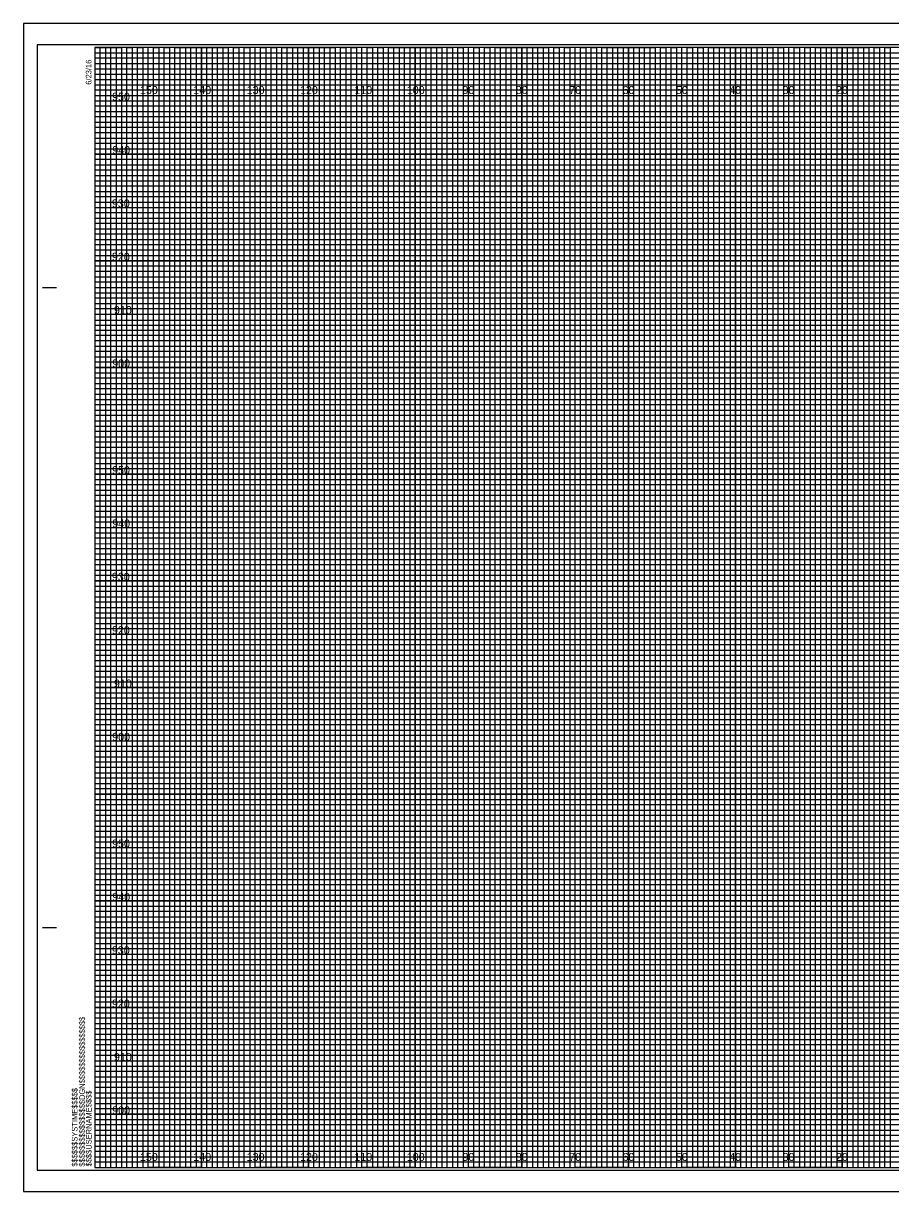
# Model space of a CAD drawing. Extents: x -13 to 323, y -4 to 3074.
# Drawn here: x -13.4 to 149.1, y 1975.5 to 2194.5 of the extents above; entities that cross this region are included whole.
import ezdxf

# ---------------------------------------------------------------- set-up
doc = ezdxf.new("R2010")
doc.units = 0
for name, color, linetype in [('Prop XS Elevation Labels', 7, 'Continuous'), ('Prop XS Offset Labels', 7, 'Continuous'), ('Sheet Cross Section CELL', 7, 'Continuous'), ('Sheet Cross Section Grid Major CELL', 7, 'Continuous'), ('Sheet Cross Section Grid Middle CELL', 7, 'Continuous'), ('Sheet Cross Section Grid Minor 1 CELL', 7, 'Continuous'), ('Sheet Cross Section Grid Minor 2 CELL', 7, 'Continuous'), ('Sheet Cutting Line CELL', 7, 'Continuous'), ('Sheet DOT Grid CELL', 7, 'Continuous'), ('Sheet Plot Border Inside CELL', 7, 'Continuous'), ('Sheet Plot Border Outside CELL', 7, 'Continuous')]:
    doc.layers.add(name, color=color, linetype=linetype)

msp = doc.modelspace()

# ---------------------------------------------------------------- linework, layer by layer
at = {"layer": 'Sheet Cross Section CELL'}
for p, q in [((-9.8, 2145), (-7.3, 2145)), ((-9.7, 2145), (-7.2, 2145)), ((-9.8, 2025), (-7.3, 2025)), ((-9.7, 2025), (-7.2, 2025)), ((0, 1980), (0, 1980)), ((0, 1980), (0, 1980)), ((0, 1980), (0, 1980)), ((0, 1980), (0, 1980)), ((0, 1980), (0, 1980)), ((0, 1980), (0, 1980)), ((0, 1980), (0, 1980))]:
    msp.add_line(p, q, dxfattribs=at)
msp.add_lwpolyline([(320, 2190), (0, 2190), (0, 1980), (320, 1980)], close=True, dxfattribs=at)
at = {"layer": 'Sheet Cross Section Grid Major CELL'}
for p, q in [((10, 2190), (0, 2190)), ((10, 1980), (10, 2190)), ((30, 2190), (20, 2190)), ((20, 2190), (20, 1980)), ((30, 1980), (30, 2190)), ((50, 2190), (40, 2190)), ((40, 2190), (40, 1980)), ((50, 1980), (50, 2190)), ((70, 2190), (60, 2190)), ((60, 2190), (60, 1980)), ((70, 1980), (70, 2190)), ((90, 2190), (80, 2190)), ((80, 2190), (80, 1980)), ((90, 1980), (90, 2190)), ((110, 2190), (100, 2190)), ((100, 2190), (100, 1980)), ((110, 1980), (110, 2190)), ((130, 2190), (120, 2190)), ((120, 2190), (120, 1980)), ((130, 1980), (130, 2190)), ((150, 2190), (140, 2190)), ((140, 2190), (140, 1980)), ((20, 1980), (10, 1980)), ((40, 1980), (30, 1980)), ((60, 1980), (50, 1980)), ((80, 1980), (70, 1980)), ((100, 1980), (90, 1980)), ((120, 1980), (110, 1980)), ((140, 1980), (130, 1980))]:
    msp.add_line(p, q, dxfattribs=at)
for points in [[(0, 2180), (320, 2180), (320, 2170), (0, 2170)], [(0, 2160), (320, 2160), (320, 2150), (0, 2150)], [(0, 2140), (320, 2140), (320, 2130), (0, 2130)], [(0, 2120), (320, 2120), (320, 2110), (0, 2110)], [(0, 2100), (320, 2100), (320, 2090), (0, 2090)], [(0, 2080), (320, 2080), (320, 2070), (0, 2070)], [(0, 2060), (320, 2060), (320, 2050), (0, 2050)], [(0, 2040), (320, 2040), (320, 2030), (0, 2030)], [(0, 2020), (320, 2020), (320, 2010), (0, 2010)], [(0, 2000), (320, 2000), (320, 1990), (0, 1990)]]:
    msp.add_lwpolyline(points, dxfattribs=at)
at = {"layer": 'Sheet Cross Section Grid Middle CELL'}
for points in [[(0, 2190), (5, 2190), (5, 1980), (15, 1980), (15, 2190), (25, 2190), (25, 1980), (35, 1980), (35, 2190), (45, 2190), (45, 1980), (55, 1980), (55, 2190), (65, 2190), (65, 1980), (75, 1980), (75, 2190), (85, 2190), (85, 1980), (95, 1980), (95, 2190), (105, 2190), (105, 1980), (115, 1980), (115, 2190), (125, 2190), (125, 1980), (135, 1980), (135, 2190), (145, 2190), (145, 1980), (155, 1980)], [(0, 2185), (275, 2185)], [(0, 2165), (320, 2165), (320, 2175), (0, 2175)], [(0, 2145), (320, 2145), (320, 2155), (0, 2155)], [(0, 2125), (320, 2125), (320, 2135), (0, 2135)], [(0, 2105), (320, 2105), (320, 2115), (0, 2115)], [(0, 2085), (320, 2085), (320, 2095), (0, 2095)], [(0, 2065), (320, 2065), (320, 2075), (0, 2075)], [(0, 2045), (320, 2045), (320, 2055), (0, 2055)], [(0, 2025), (320, 2025), (320, 2035), (0, 2035)], [(0, 2005), (320, 2005), (320, 2015), (0, 2015)], [(0, 1985), (320, 1985), (320, 1995), (0, 1995)]]:
    msp.add_lwpolyline(points, dxfattribs=at)
at = {"layer": 'Sheet Cross Section Grid Minor 1 CELL'}
for p, q in [((0, 2189), (260, 2189)), ((260, 2187.98), (0, 2187.98)), ((0, 2187.98), (0, 2187)), ((0, 2187), (260, 2187)), ((260, 2185.89), (0, 2185.89)), ((0, 2185.89), (0, 2184)), ((0, 2184), (320, 2184))]:
    msp.add_line(p, q, dxfattribs=at)
for points in [[(0, 2183), (270, 2183), (320, 2183), (320, 2182), (0, 2182)], [(0, 2181), (320, 2181), (320, 2179), (0, 2179)], [(0, 2178), (320, 2178), (320, 2177), (0, 2176.98)], [(0, 2176), (320, 2176), (320, 2174), (0, 2174)], [(0, 2173), (320, 2173), (320, 2172), (0, 2172)], [(0, 2171), (320, 2171), (320, 2169), (0, 2169)], [(0, 2168), (320, 2168), (320, 2167), (0, 2167)], [(0, 2166), (320, 2166), (320, 2164), (0, 2164)], [(0, 2163), (320, 2163), (320, 2162), (0, 2162)], [(0, 2161), (320, 2161), (320, 2159), (0, 2159)], [(0, 2158), (320, 2158), (320, 2157), (0, 2157)], [(0, 2156), (320, 2156), (320, 2153.95), (320, 2153), (320, 2152), (0, 2152)], [(0, 2154), (320, 2154), (320, 2153), (0, 2153)], [(0, 2151), (320, 2151), (320, 2149), (0, 2149.03)], [(0, 2149.03), (320, 2149), (320, 2148), (0, 2148)], [(0, 2147), (320, 2147), (320, 2146), (0, 2146)], [(0, 2144), (320, 2144), (320, 2143), (0, 2143)], [(0, 2142), (320, 2142), (320, 2141), (0, 2141)], [(-0.07, 2138.89), (320, 2138.89), (320, 2137.88), (-0.07, 2137.88)], [(0, 2137), (320, 2137), (320, 2136), (0, 2136)], [(0, 2134), (320, 2134), (320, 2133), (0, 2133)], [(0, 2132), (320, 2132), (320, 2131), (0, 2131)], [(0, 2129), (320, 2129), (320, 2128), (0, 2128)], [(0, 2127), (320, 2127), (320, 2126), (0, 2126)], [(0, 2124), (320, 2124), (320, 2123), (0, 2123)], [(0, 2122), (320, 2122), (320, 2121), (0, 2121)], [(0, 2119), (320, 2119), (319.99, 2117.98), (0, 2118)], [(0, 2117), (320, 2117), (320, 2116), (0, 2116)], [(0, 2114), (320, 2114), (320, 2113), (0, 2113)], [(0, 2112), (320, 2112), (320, 2111), (0, 2111)], [(0, 2109), (320, 2109), (320, 2108), (0, 2108)], [(0, 2107), (320, 2107), (320, 2106), (0, 2106)], [(0, 2104), (320, 2104), (320, 2103), (0, 2103)], [(0, 2102), (320, 2102), (320, 2101), (0, 2101)], [(0, 2099), (320, 2099), (320, 2098), (0, 2098)], [(0, 2096.99), (320.07, 2096.91), (320, 2096), (0, 2096)], [(0, 2094), (320, 2094), (320, 2093), (0, 2093)], [(0, 2092), (320, 2092), (320, 2091), (0, 2091)], [(0, 2089), (320, 2089), (320, 2088), (0, 2088)], [(0, 2087), (320, 2087), (320, 2086), (0, 2086)], [(0, 2084), (320, 2084), (320, 2083), (0, 2083)], [(0, 2082), (320, 2082), (320, 2081), (0, 2081)], [(0, 2079), (320, 2079), (320, 2078), (0, 2078)], [(0, 2077), (320, 2077), (320, 2076), (0, 2076)], [(0, 2074), (320, 2074), (320, 2073), (0, 2073)], [(0, 2072), (320, 2072), (320, 2071), (0, 2071)], [(0, 2069), (320, 2069), (320, 2068), (0, 2068)], [(0, 2067), (320, 2067), (320, 2066), (0, 2066)], [(0, 2064), (320, 2064), (320, 2063), (0, 2063)], [(0, 2062), (320, 2062), (320, 2061), (0, 2061)], [(0, 2059), (320, 2059), (319.99, 2057.98), (0, 2058)], [(0, 2057), (320, 2057), (320, 2056), (0, 2056)], [(0, 2054), (320, 2054), (320, 2053), (0, 2053)], [(0, 2052), (320, 2052), (320, 2051), (0, 2051)], [(0, 2049), (320, 2049), (320, 2048), (0, 2048)], [(0, 2047), (320, 2047), (320, 2046), (0, 2046)], [(0, 2044), (320, 2044), (320, 2043), (0, 2043)], [(0, 2042), (320, 2042), (320, 2041), (0, 2041)], [(0, 2039), (320, 2039), (320, 2038), (0, 2038)], [(0, 2036.99), (320.07, 2036.91), (320, 2036), (0, 2036)], [(0, 2034), (320, 2034), (320, 2033), (0, 2033)], [(0, 2032), (320, 2032), (320, 2031), (0, 2031)], [(0, 2029), (320, 2029), (320, 2028), (0, 2028)], [(0, 2027), (320, 2027), (320, 2026), (0, 2026)], [(0, 2024), (320, 2024), (320, 2023), (0, 2023)], [(0, 2022), (320, 2022), (320, 2021), (0, 2021)], [(0, 2019), (320, 2019), (320, 2018), (0, 2018)], [(0, 2017), (320, 2017), (320, 2016), (0, 2016)], [(0, 2014), (320, 2014), (320, 2013), (0, 2013)], [(0, 2012), (320, 2012), (320, 2011), (0, 2011)], [(0, 2009), (320, 2009), (320, 2008), (0, 2008)], [(0, 2007), (320, 2007), (320, 2006), (0, 2006)], [(0, 2004), (320, 2004), (320, 2003), (0, 2003)], [(0, 2002), (320, 2002), (320, 2001), (0, 2001)], [(0, 1999), (320, 1999), (320, 1998), (0, 1998)], [(0, 1997), (320, 1997), (320, 1996), (0, 1996)], [(0, 1994), (320, 1994), (320, 1993), (0, 1993)], [(0, 1992), (320, 1992), (320, 1991), (0, 1991)], [(0, 1989), (320, 1989), (320, 1988), (0, 1988)], [(0, 1987), (320, 1987), (320, 1986), (0, 1986)], [(0, 1984), (320, 1984), (320, 1983), (0, 1983)], [(0, 1982), (320, 1982), (320, 1981), (0, 1981)]]:
    msp.add_lwpolyline(points, dxfattribs=at)
at = {"layer": 'Sheet Cross Section Grid Minor 2 CELL'}
for points in [[(0, 1980), (1, 1980), (1, 2190), (2, 2190), (2, 1980)], [(2, 1980), (3, 1980), (3, 2190), (4, 2190), (4, 1980)], [(5, 1980), (6, 1980), (6, 2190), (7, 2190), (7, 1980)], [(7, 1980), (8, 1980), (8, 2190), (9, 2190), (9, 1980)], [(10, 1980), (11, 1980), (11, 2190), (12, 2190), (12, 1980)], [(12, 1980), (13, 1980), (13, 2190), (14, 2190), (14, 1980)], [(15, 1980), (16, 1980), (16, 2190), (17, 2190), (17, 1980)], [(17, 1980), (18, 1980), (18, 2190), (19, 2190), (19, 1980)], [(20, 1980), (21, 1980), (21, 2190), (22, 2190), (22, 1980)], [(22, 1980), (23, 1980), (23, 2190), (24, 2190), (24, 1980)], [(25, 1980), (26, 1980), (26, 2190), (27, 2190), (27, 1980)], [(27, 1980), (28, 1980), (28, 2190), (29, 2190), (29, 1980)], [(30, 1980), (31, 1980), (31, 2190), (32, 2190), (32, 1980)], [(32, 1980), (33, 1980), (33, 2190), (34, 2190), (34, 1980)], [(35, 1980), (36, 1980), (36, 2190), (37, 2190), (37, 1980)], [(37, 1980), (38, 1980), (38, 2190), (39, 2190), (39, 1980)], [(40, 1980), (41, 1980), (41, 2190), (42, 2190), (42, 1980)], [(42, 1980), (43, 1980), (43, 2190), (44, 2190), (44, 1980)], [(45, 1980), (46, 1980), (46, 2190), (47, 2190), (47, 1980)], [(47, 1980), (48, 1980), (48, 2190), (49, 2190), (49, 1980)], [(50, 1980), (51, 1980), (51, 2190), (52, 2190), (52, 1980)], [(52, 1980), (53, 1980), (53, 2190), (54, 2190), (54, 1980)], [(55, 1980), (56, 1980), (56, 2190), (57, 2190), (57, 1980)], [(57, 1980), (58, 1980), (58, 2190), (59, 2190), (59, 1980)], [(60, 1980), (61, 1980), (61, 2190), (62, 2190), (62, 1980)], [(62, 1980), (63, 1980), (63, 2190), (64, 2190), (64, 1980)], [(65, 1980), (66, 1980), (66, 2190), (67, 2190), (67, 1980)], [(67, 1980), (68, 1980), (68, 2190), (69, 2190), (69, 1980)], [(70, 1980), (71, 1980), (71, 2190), (72, 2190), (72, 1980)], [(72, 1980), (73, 1980), (73, 2190), (74, 2190), (74, 1980)], [(75, 1980), (76, 1980), (76, 2190), (77, 2190), (77, 1980)], [(77, 1980), (78, 1980), (78, 2190), (79, 2190), (79, 1980)], [(80, 1980), (81, 1980), (81, 2190), (82, 2190), (82, 1980)], [(82, 1980), (83, 1980), (83, 2190), (84, 2190), (84, 1980)], [(85, 1980), (86, 1980), (86, 2190), (87, 2190), (87, 1980)], [(87, 1980), (88, 1980), (88, 2190), (89, 2190), (89, 1980)], [(90, 1980), (91, 1980), (91, 2190), (92, 2190), (92, 1980)], [(92, 1980), (93, 1980), (93, 2190), (94, 2190), (94, 1980)], [(95, 1980), (96, 1980), (96, 2190), (97, 2190), (97, 1980)], [(97, 1980), (98, 1980), (98, 2190), (99, 2190), (99, 1980)], [(100, 1980), (101, 1980), (101, 2190), (102, 2190), (102, 1980)], [(102, 1980), (103, 1980), (103, 2190), (104, 2190), (104, 1980)], [(105, 1980), (106, 1980), (106, 2190), (107, 2190), (107, 1980)], [(107, 1980), (108, 1980), (108, 2190), (109, 2190), (109, 1980)], [(110, 1980), (111, 1980), (111, 2190), (112, 2190), (112, 1980)], [(112, 1980), (113, 1980), (113, 2190), (114, 2190), (114, 1980)], [(115, 1980), (116, 1980), (116, 2190), (117, 2190), (117, 1980)], [(117, 1980), (118, 1980), (118, 2190), (119, 2190), (119, 1980)], [(120, 1980), (121, 1980), (121, 2190), (122, 2190), (122, 1980)], [(122, 1980), (123, 1980), (123, 2190), (124, 2190), (124, 1980)], [(125, 1980), (126, 1980), (126, 2190), (127, 2190), (127, 1980)], [(127, 1980), (128, 1980), (128, 2190), (129, 2190), (129, 1980)], [(130, 1980), (131, 1980), (131, 2190), (132, 2190), (132, 1980)], [(132, 1980), (133, 1980), (133, 2190), (134, 2190), (134, 1980)], [(135, 1980), (136, 1980), (136, 2190), (137, 2190), (137, 1980)], [(137, 1980), (138, 1980), (138, 2190), (139, 2190), (139, 1980)], [(140, 1980), (141, 1980), (141, 2190), (142, 2190), (142, 1980)], [(142, 1980), (143, 1980), (143, 2190), (144, 2190), (144, 1980)], [(145, 1980), (146, 1980), (146, 2190), (147, 2190), (147, 1980)], [(147, 1980), (148, 1980), (148, 2190), (149, 2190), (149, 1980)]]:
    msp.add_lwpolyline(points, dxfattribs=at)
at = {"layer": 'Sheet Cutting Line CELL'}
for p, q in [((323.3, 2194.5), (-13.4, 2194.5)), ((-13.4, 2194.5), (-13.4, 1975.5)), ((-13.4, 1975.5), (323.3, 1975.5))]:
    msp.add_line(p, q, dxfattribs=at)
at = {"layer": 'Sheet DOT Grid CELL'}
for p, q in [((10, 1980), (10, 2190)), ((20, 1980), (20, 2190)), ((30, 1980), (30, 2190)), ((40, 1980), (40, 2190)), ((50, 1980), (50, 2190)), ((60, 1980), (60, 2190)), ((70, 1980), (70, 2190)), ((80, 1980), (80, 2190)), ((90, 1980), (90, 2190)), ((100, 1980), (100, 2190)), ((110, 1980), (110, 2190)), ((120, 1980), (120, 2190)), ((130, 1980), (130, 2190)), ((140, 1980), (140, 2190)), ((0, 2180), (320, 2180)), ((0, 2170), (320, 2170)), ((0, 2160), (320, 2160)), ((0, 2150), (320, 2150)), ((0, 2140), (320, 2140)), ((0, 2130), (320, 2130)), ((0, 2120), (320, 2120)), ((0, 2110), (320, 2110)), ((0, 2100), (320, 2100)), ((0, 2090), (320, 2090)), ((0, 2080), (320, 2080)), ((0, 2070), (320, 2070)), ((0, 2060), (320, 2060)), ((0, 2050), (320, 2050)), ((0, 2040), (320, 2040)), ((0, 2030), (320, 2030)), ((0, 2020), (320, 2020)), ((0, 2010), (320, 2010)), ((0, 2000), (320, 2000)), ((0, 1990), (320, 1990))]:
    msp.add_line(p, q, dxfattribs=at)
at = {"layer": 'Sheet Plot Border Inside CELL'}
msp.add_lwpolyline([(-10.8, 1979.5), (322.4, 1979.5), (322.4, 2190.5), (-10.8, 2190.5)], close=True, dxfattribs=at)
at = {"layer": 'Sheet Plot Border Outside CELL'}
msp.add_lwpolyline([(-13.4, 1975.5), (323.3, 1975.5), (323.3, 2194.5), (-13.4, 2194.5)], close=True, dxfattribs=at)

# ---------------------------------------------------------------- texts
at = {"layer": 'Prop XS Elevation Labels'}
for s, p in [('950', (3.22, 2180)), ('940', (3.26, 2170)), ('930', (3.18, 2160)), ('920', (3.19, 2150)), ('910', (3.57, 2140)), ('900', (3.24, 2130)), ('950', (3.22, 2110)), ('940', (3.26, 2100)), ('930', (3.18, 2090)), ('920', (3.19, 2080)), ('910', (3.57, 2070)), ('900', (3.24, 2060)), ('950', (3.22, 2040)), ('940', (3.26, 2030)), ('930', (3.18, 2020)), ('920', (3.19, 2010)), ('910', (3.57, 2000)), ('900', (3.24, 1990))]:
    msp.add_text(s, height=1.5, dxfattribs=at).set_placement(p)
at = {"layer": 'Prop XS Offset Labels'}
for s, p in [('150', (8.44, 2181.25)), ('140', (18.44, 2181.25)), ('130', (28.44, 2181.25)), ('120', (38.44, 2181.25)), ('110', (48.62, 2181.25)), ('100', (58.44, 2181.25)), ('90', (68.86, 2181.25)), ('80', (78.86, 2181.25)), ('70', (88.86, 2181.25)), ('60', (98.86, 2181.25)), ('50', (108.86, 2181.25)), ('40', (118.86, 2181.25)), ('30', (128.86, 2181.25)), ('20', (138.86, 2181.25)), ('150', (8.44, 1981.25)), ('140', (18.44, 1981.25)), ('130', (28.44, 1981.25)), ('120', (38.44, 1981.25)), ('110', (48.62, 1981.25)), ('100', (58.44, 1981.25)), ('90', (68.86, 1981.25)), ('80', (78.86, 1981.25)), ('70', (88.86, 1981.25)), ('60', (98.86, 1981.25)), ('50', (108.86, 1981.25)), ('40', (118.86, 1981.25)), ('30', (128.86, 1981.25)), ('20', (138.86, 1981.25))]:
    msp.add_text(s, height=1.5, dxfattribs=at).set_placement(p)
at = {"layer": 'Sheet Cross Section CELL'}
for s, p in [('6/23/16', (-0.65, 2183)), ('$$$$$$$$$$$$$$$$DGN$$$$$$$$$$$$$$$$', (-1.88, 1980.18)), ('$$$$$$SYSTIME$$$$$', (-3.26, 1980.18)), ('$$$$USERNAME$$$$', (-0.62, 1980.23))]:
    msp.add_text(s, height=1.05, rotation=90, dxfattribs=at).set_placement(p)

doc.saveas('drawing.dxf')
